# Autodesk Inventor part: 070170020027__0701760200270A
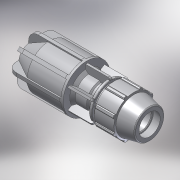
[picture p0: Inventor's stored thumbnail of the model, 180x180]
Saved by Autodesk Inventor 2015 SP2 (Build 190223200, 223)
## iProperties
Created: 2017-02
Part Number: 070170020027__0701760200270A
Material: PVC-Piping
Description: PLASSON PLASS4 COUPLING 20-27*20
Document SubType Name: Modeling
Designer: KIM
Mass: 92.6774 g
Surface Area: 199.44 cm^2
Volume: 66.1981 cm^3
Density: 1.4 g/cm^3
Appearance: Smooth - White
Author: KIM
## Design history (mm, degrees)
derived "070170.ipt"
feature "Solid1::070170.ipt"
tag "TaggingFeature1"
body "Solid1"
other parameters: "d4" = 12.14286, "d5" = 20.3, "d7" = 48, "d8" = 28.04092, "d9" = 11.57143, "d11" = 4.25, "d12" = 38.4, "d13" = 120 deg, "d15" = 12 deg, "d16" = 43.2, "d18" = 1, "d19" = 35 deg, "d20" = 17.5 deg, "d21" = 44.64, "d23" = 0, "d25" = 360 deg, "d27" = 0.96, "d42" = 26.1, "d43" = 1.44, "d46" = 0.6, "d53" = 0.4, "d67" = 2.4, "d70" = 18, "d71" = 58, "d74" = 180 deg, "d75" = 27, "d76" = 71, "d80" = 18, "d84" = 67.45, "d85" = 135 deg, "d86" = 3.55, "d89" = 3.55, "d90" = 135 deg, "d94" = 3.55, "d97" = 3.84, "d98" = 0, "d100" = 360 deg, "d102" = 78.1, "d103" = 14.2, "d104" = 5.68, "d105" = 0, "d110" = 85, "d112" = 102, "d113" = 28.9, "d114" = 68, "d115" = 42.6, "d116" = 102, "d117" = 4.25, "d118" = 24, "d119" = 2.4, "d120" = 0, "d121" = 2.4, "d123" = 360 deg, "E_" = 48, "A_" = 81, "l_" = 58, "d_1" = 27, "E_1" = 71, "l_1" = 85, "d106" = 28.04092
